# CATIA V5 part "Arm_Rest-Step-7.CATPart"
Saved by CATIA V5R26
Part number: Arm_Rest
Bounding box of the stored display mesh (mm): x 743.798 to 1432.298, y -782.976 to 0, z 330.43 to 551.996
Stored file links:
  D:\LinkedIn Learning\NURBS\CATIA\Class Parts\Arm_Rest-Step-8.CATPart
  D:\LinkedIn Learning\NURBS\Arm_Rest.CATPart
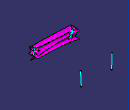
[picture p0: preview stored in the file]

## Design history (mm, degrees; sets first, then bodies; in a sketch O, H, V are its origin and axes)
AxisSystem1: origin (0, 0, 0), X (1, 0, 0), Y (0, 1, 0), Z (0, 0, 1)
StDynAnalysisRootNodeFeature1 "CATStDynAnalysisRootNodeName"
Set1 "REF DATA"
  CLDGeom1 "TOP"
  CLDGeom2 "FRONT"
  CLDGeom3 "AFT_BLEND"
  CLDGeom4 "END_AFT"
  CLDGeom5 "FORWARD_BLEND"
  CLDGeom6 "BOTTOM"
  CLDGeom7 "END_FORWARD"
  CLDGeom8 "UPPER_BLENDS"
  CLDGeom9 "LOWER_BLENDS"
  DatumSurface1 "DOOR_TRIM_SURFACE"
Set2 "FORM"
  Set3 "SLABS"
    DatumSurface2 to DatumSurface6
  Set4 "CURVES"
    St3DCurveFeature1 "CATSt3DCurveFeatureName": Order 6, CreationType 1, ClosureMode false, ConstructionPoints ({point type Coord, X 863.1168, Y 0, Z 551.1449}; {point type Coord, X 868.9503, Y 0, Z 330.43}), SymmetryMode false
    St3DCurveFeature2 "CATSt3DCurveFeatureName": Order 6, CreationType 1, ClosureMode false, ConstructionPoints ({point type Coord, X 1369.3867, Y 0, Z 551.9965}; {point type Coord, X 1358.4038, Y 0, Z 335.6826}), SymmetryMode false
    Intersect1: ToIntersect1 DatumSurface4, ToIntersect2 DatumSurface5
    Intersect2: ToIntersect1 DatumSurface6, ToIntersect2 DatumSurface4
    CurvePar1: Offset Intersect2, Support DatumSurface6, Offset2 0, Offset1 30
    CurvePar2: Offset Intersect1, Support DatumSurface5, Offset2 50, Offset1 20
    Project1: ToProject St3DCurveFeature1, Support DatumSurface4, Direction edge [YZ plane of AxisSystem1 | XY plane of AxisSystem1]
    Project2: ToProject St3DCurveFeature2, Support DatumSurface4, Direction edge [YZ plane of AxisSystem1 | XY plane of AxisSystem1]
    Project3: ToProject St3DCurveFeature2, Support StTopoTypeFeature3, Direction edge [YZ plane of AxisSystem1 | XY plane of AxisSystem1]
    Project4: ToProject St3DCurveFeature1, Support StTopoTypeFeature3, Direction edge [YZ plane of AxisSystem1 | XY plane of AxisSystem1]
    Intersect3: ToIntersect1 edge of StTopoTypeFeature1, ToIntersect2 CurvePar2
    Intersect4: ToIntersect1 edge of StTopoTypeFeature2, ToIntersect2 CurvePar1
    Project5: ToProject Intersect4, Support edge of StTopoTypeFeature2
    Project6: ToProject Intersect3, Support edge of StTopoTypeFeature1
    Line1: type PtPt, FirstPoint Intersect3, SecondPoint Project6, Support StTopoTypeFeature1
    Line2: type PtPt, FirstPoint Intersect4, SecondPoint Project5, Support StTopoTypeFeature2
    Curve1: Elements (Intersect4; vertex of Project3), Support Blend2
    Curve2: Elements (Project5; vertex of Project3), Support DatumSurface2
    Curve3: Elements (vertex of Project4; Intersect3), Support Blend1
    Curve4: Elements (vertex of Project4; Project6), Support DatumSurface2
  Set5 "BLENDS"
    Blend1: StartLimit {blendlimit Curve Project1, Support DatumSurface4, TensionValues 1.1}, EndLimit {blendlimit Curve CurvePar2, Support DatumSurface5, TensionValues 1}
    Blend2: StartLimit {blendlimit Curve CurvePar1, Support DatumSurface6, TensionValues 0.9}, EndLimit {blendlimit Curve Project2, Support DatumSurface4, TensionValues 0.8}
    StTopoTypeFeature1 "CATStTopoTypeFeatureName": Children 15
    StTopoTypeFeature2 "CATStTopoTypeFeatureName": Children 35
    StTopoTypeFeature3 "CATStTopoTypeFeatureName": nls://CATStFeaturesStartUpsNLS/TopoVarRadiCke 35, nls://CATStFeaturesStartUpsNLS/TopoVarRadiCke 15
Body1 (main body)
